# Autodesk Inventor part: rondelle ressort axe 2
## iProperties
Author: Administrateur
Created: 2001-04
Part Number: rondelle ressort axe 2
Material: Par défaut
Document SubType Name: Tôlerie
Designer: Administrateur
Control State: 0
Master: False
Checked Out: False
PropertySet Name: Design Tracking Control
Shininess: 20.0
PropertySet Name: _Private Model Information
Length Units: 11269
Angle Units: 11283
Time Units: 11279
Mass Units: 11290
Length Display Precision: 3
Angle Display Precision: 2
Compacted: False
Density: 0.0
Volumn: 0.0
Area: 0.0
PropertySet Name: Model Information
